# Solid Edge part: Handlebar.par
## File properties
Username: m_hel
Author: m_hel
Template: Iso Metric Part.par
Last saved by: m_hel
Revision: 4
Application: Solid Edge
Accuracy: 0,990
Material: Chrome
Face Style: Chrome
Fill Style: Normal
Virtual Style: Normal
Grouping: Uncategorized
LibraryName: Custom Materials
Coef. of Thermal Exp: 0.0
Thermal Conductivity: 0.0
Specific Heat: 0.0
Modulus of Elasticity: 0.0
Poisson's Ratio: 0.0
Yield Stress: 0.0
Ultimate Stress: 0.0
Elongation: 0.0
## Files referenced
..\Redfisher18.asm
G:\OneDriveTemp\OneDrive\Dokumendid\TLÜ tööd\3D Modelleerimine\3d modelling\veesõiduk\Deck1.par
iduk\Deck1.par
iduk\Redfisher18.asm
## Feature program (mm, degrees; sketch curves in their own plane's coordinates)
sketch for "unnamed Protrusion 1" plane through (-845, -976.906, 25) normal (0.5, 0.866025, 0) x-axis (-0.866025, 0.5, 0)
  circle centre (0, 0) radius 22.5
extrude "unnamed Protrusion 1" add finite 5 along +normal
body pattern "unnamed BodyPattern 1"
pattern "unnamed Pattern 1"
swept protrusion "SweptProtrusion_2"
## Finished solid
Body 1: solid body, 9 faces, 8 edges, 0 vertices.
  Faces by surface: plane 4, cylinder 3, torus 2
  Edges by curve: circle 8
Body 2: sheet body, 3 faces, 10 edges, 8 vertices.
  Faces by surface: plane 3
  Edges by curve: line 10
Bounding box of the edges (mm; curved faces can reach further): 80.000 x 242.376 x 50.000, from (-885, -1000, 0) to (-805, -757.624, 50).
Cylindrical faces by radius (mm): R15 x1, R22.5 x2
Toroidal faces (ring radius, tube radius in mm): R55.9808 r15 x2
Planar faces by outward normal: oblique 4
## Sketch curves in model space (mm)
arc centre (-890.9808, -944.5855, 0) radius 55.9808 from (-842.5, -972.5759, 0) through (-836.9075, -959.0744, 0) to (-835, -944.5855, 0)
line (-835, -944.5855, 0) -> (-835, -813.0385, 0)
arc centre (-890.9808, -813.0385, 0) radius 55.9808 from (-842.5, -785.0481, 0) through (-836.9075, -798.5496, 0) to (-835, -813.0385, 0)
line (-885, -878.812, 0) -> (-885, -878.812, 50)
line (-885, -878.812, 0) -> (-780.0625, -878.812, 0)
circle centre (-842.5, -972.5759, 25) radius 15
circle centre (-845, -976.906, 25) radius 22.5
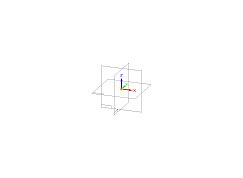
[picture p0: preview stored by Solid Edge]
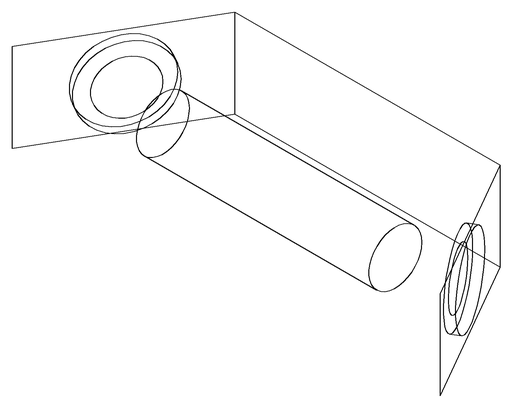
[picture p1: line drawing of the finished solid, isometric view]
